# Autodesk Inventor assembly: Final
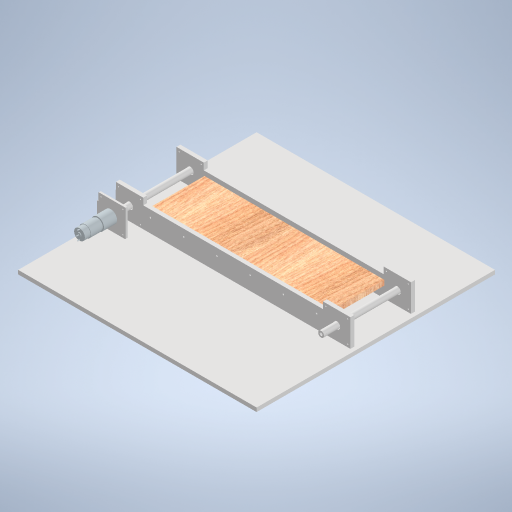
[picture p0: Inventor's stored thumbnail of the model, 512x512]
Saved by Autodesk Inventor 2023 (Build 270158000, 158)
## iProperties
Created: 2022-06
Part Number: Final
Document SubType Name: Assembly
Designer: prana_p9lsmih
Author: prana_p9lsmih
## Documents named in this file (8)
- E:\PRANAV\ENGINEERING EXPLORATION\VIRTUAL IMPLEMENTATION\3D Models\Final.iam
- E:\PRANAV\ENGINEERING EXPLORATION\VIRTUAL IMPLEMENTATION\3D Models\BASE.ipt
- E:\PRANAV\ENGINEERING EXPLORATION\VIRTUAL IMPLEMENTATION\3D Models\conveyor belt sideplank.ipt
- E:\PRANAV\ENGINEERING EXPLORATION\VIRTUAL IMPLEMENTATION\3D Models\Motor clamp p1.ipt
- E:\PRANAV\ENGINEERING EXPLORATION\VIRTUAL IMPLEMENTATION\3D Models\support.ipt
- E:\PRANAV\ENGINEERING EXPLORATION\VIRTUAL IMPLEMENTATION\3D Models\motor.ipt
- E:\PRANAV\ENGINEERING EXPLORATION\VIRTUAL IMPLEMENTATION\3D Models\shaft.ipt
- E:\PRANAV\ENGINEERING EXPLORATION\VIRTUAL IMPLEMENTATION\3D Models\belt support.ipt
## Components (11 placed, 7 different names)
1. BASE:1 — Mate:1, Mate:2, Mate:11, Mate:12, Mate:15, Mate:16, Mate:17, Mate:18, Mate:19
2. conveyor belt sideplank:1 — Mate:1, Mate:3, Mate:4, Mate:5, Mate:6, Mate:7, Mate:8, Mate:9, Mate:10, Mate:23, Mate:24, Mate:25, Mate:26
3. conveyor belt sideplank:2 — Mate:2, Mate:3, Mate:4, Mate:5, Mate:6, Mate:13, Mate:14, Flush:1, Flush:2
4. Motor clamp p1:1 — Mate:7, Mate:8, Mate:9, Mate:10, Mate:20, Mate:21
5. support:1 — Mate:18, Mate:19
6. support:2 — Mate:15, Mate:16, Mate:17
7. support:3 — Mate:11, Mate:12, Mate:13, Mate:14
8. motor:1 — Mate:20, Mate:21, Mate:22
9. shaft:1 — Mate:22, Flush:1
10. shaft:2 — Mate:23, Flush:2
11. belt support:1 — Mate:24, Mate:25, Mate:26
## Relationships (28: Mate 26, Flush 2)
- Mate:1: BASE:1 ↔ conveyor belt sideplank:1
- Mate:2: BASE:1 ↔ conveyor belt sideplank:2
- Mate:3: conveyor belt sideplank:1 ↔ conveyor belt sideplank:2
- Mate:4: conveyor belt sideplank:1 ↔ conveyor belt sideplank:2
- Mate:5: conveyor belt sideplank:1 ↔ conveyor belt sideplank:2
- Mate:6: conveyor belt sideplank:1 ↔ conveyor belt sideplank:2
- Mate:7: conveyor belt sideplank:1 ↔ Motor clamp p1:1
- Mate:8: conveyor belt sideplank:1 ↔ Motor clamp p1:1
- Mate:9: conveyor belt sideplank:1 ↔ Motor clamp p1:1
- Mate:10: conveyor belt sideplank:1 ↔ Motor clamp p1:1
- Mate:11: BASE:1 ↔ support:3
- Mate:12: BASE:1 ↔ support:3
- Mate:13: conveyor belt sideplank:2 ↔ support:3
- Mate:14: conveyor belt sideplank:2 ↔ support:3
- Mate:15: BASE:1 ↔ support:2
- Mate:16: BASE:1 ↔ support:2
- Mate:17: BASE:1 ↔ support:2
- Mate:18: BASE:1 ↔ support:1
- Mate:19: BASE:1 ↔ support:1
- Mate:20: Motor clamp p1:1 ↔ motor:1
- Mate:21: Motor clamp p1:1 ↔ motor:1
- Mate:22: motor:1 ↔ shaft:1
- Flush:1: conveyor belt sideplank:2 ↔ shaft:1
- Mate:23: conveyor belt sideplank:1 ↔ shaft:2
- Flush:2: conveyor belt sideplank:2 ↔ shaft:2
- Mate:24: conveyor belt sideplank:1 ↔ belt support:1
- Mate:25: conveyor belt sideplank:1 ↔ belt support:1
- Mate:26: conveyor belt sideplank:1 ↔ belt support:1
